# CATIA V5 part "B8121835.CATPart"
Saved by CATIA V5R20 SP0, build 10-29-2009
Part number: B8121835
Revision: 9
Definition: design
Nomenclature: B8121835
Source: made
Description: NOT SPECIFIED
Bounding box of the stored display mesh (mm): x -17.5 to 17.5, y -17.5 to 17.5, z -11 to 24
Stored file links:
  C:\Users\Utente\Desktop\3D files B812\B8121835.CATPart
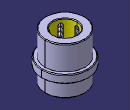
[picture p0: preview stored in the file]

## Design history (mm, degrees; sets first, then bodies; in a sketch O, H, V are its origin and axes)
Body1 "MANIFOLD_SOLID_BREP #38" (main body)
  Solid1: solid without history
Body2 "MANIFOLD_SOLID_BREP #76"
  Solid2: solid without history
Body3 "MANIFOLD_SOLID_BREP #114"
  Solid3: solid without history
Body4 "MANIFOLD_SOLID_BREP #152"
  Solid4: solid without history
Body5 "MANIFOLD_SOLID_BREP #190"
  Solid5: solid without history
Body6 "MANIFOLD_SOLID_BREP #228"
  Solid6: solid without history
Body7 "MANIFOLD_SOLID_BREP #266"
  Solid7: solid without history
Body8 "MANIFOLD_SOLID_BREP #304"
  Solid8: solid without history
Body9 "MANIFOLD_SOLID_BREP #2006"
  Solid9: solid without history
Body10 "MANIFOLD_SOLID_BREP #2044"
  Solid10: solid without history
Body11 "MANIFOLD_SOLID_BREP #2082"
  Solid11: solid without history
Body12 "MANIFOLD_SOLID_BREP #2120"
  Solid12: solid without history
Body13 "MANIFOLD_SOLID_BREP #2158"
  Solid13: solid without history
Body14 "MANIFOLD_SOLID_BREP #2196"
  Solid14: solid without history
Body15 "MANIFOLD_SOLID_BREP #2234"
  Solid15: solid without history
Body16 "MANIFOLD_SOLID_BREP #2272"
  Solid16: solid without history
Body17 "MANIFOLD_SOLID_BREP #2310"
  Solid17: solid without history
Body18 "MANIFOLD_SOLID_BREP #2348"
  Solid18: solid without history
Body19 "MANIFOLD_SOLID_BREP #2386"
  Solid19: solid without history
Body20 "MANIFOLD_SOLID_BREP #2424"
  Solid20: solid without history
Body21 "MANIFOLD_SOLID_BREP #2462"
  Solid21: solid without history
Body22 "MANIFOLD_SOLID_BREP #2500"
  Solid22: solid without history
Body23 "MANIFOLD_SOLID_BREP #2538"
  Solid23: solid without history
Body24 "MANIFOLD_SOLID_BREP #2576"
  Solid24: solid without history
Body25 "MANIFOLD_SOLID_BREP #2614"
  Solid25: solid without history
Body26 "MANIFOLD_SOLID_BREP #2652"
  Solid26: solid without history
Body27 "MANIFOLD_SOLID_BREP #2690"
  Solid27: solid without history
Body28 "MANIFOLD_SOLID_BREP #2728"
  Solid28: solid without history
Body29 "MANIFOLD_SOLID_BREP #2766"
  Solid29: solid without history
Body30 "MANIFOLD_SOLID_BREP #2804"
  Solid30: solid without history
Body31 "MANIFOLD_SOLID_BREP #2842"
  Solid31: solid without history
Body32 "MANIFOLD_SOLID_BREP #2880"
  Solid32: solid without history
Body33 "MANIFOLD_SOLID_BREP #2918"
  Solid33: solid without history
Body34 "MANIFOLD_SOLID_BREP #2956"
  Solid34: solid without history
Body35 "MANIFOLD_SOLID_BREP #2994"
  Solid35: solid without history
Body36 "MANIFOLD_SOLID_BREP #3032"
  Solid36: solid without history
Body37 "MANIFOLD_SOLID_BREP #3070"
  Solid37: solid without history
Body38 "MANIFOLD_SOLID_BREP #3108"
  Solid38: solid without history
Body39 "MANIFOLD_SOLID_BREP #3146"
  Solid39: solid without history
Body40 "MANIFOLD_SOLID_BREP #3184"
  Solid40: solid without history
Body41 "MANIFOLD_SOLID_BREP #3222"
  Solid41: solid without history
Body42 "MANIFOLD_SOLID_BREP #3260"
  Solid42: solid without history
Body43 "MANIFOLD_SOLID_BREP #3298"
  Solid43: solid without history
Body44 "MANIFOLD_SOLID_BREP #3336"
  Solid44: solid without history
Body45 "MANIFOLD_SOLID_BREP #3374"
  Solid45: solid without history
Body46 "MANIFOLD_SOLID_BREP #3412"
  Solid46: solid without history
Body47 "MANIFOLD_SOLID_BREP #3450"
  Solid47: solid without history
Body48 "MANIFOLD_SOLID_BREP #3488"
  Solid48: solid without history
Body49 "MANIFOLD_SOLID_BREP #3526"
  Solid49: solid without history
Body50 "MANIFOLD_SOLID_BREP #3564"
  Solid50: solid without history
Body51 "MANIFOLD_SOLID_BREP #3602"
  Solid51: solid without history
Body52 "MANIFOLD_SOLID_BREP #3640"
  Solid52: solid without history
Body53 "MANIFOLD_SOLID_BREP #3678"
  Solid53: solid without history
Body54 "MANIFOLD_SOLID_BREP #3716"
  Solid54: solid without history
Body55 "MANIFOLD_SOLID_BREP #3754"
  Solid55: solid without history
